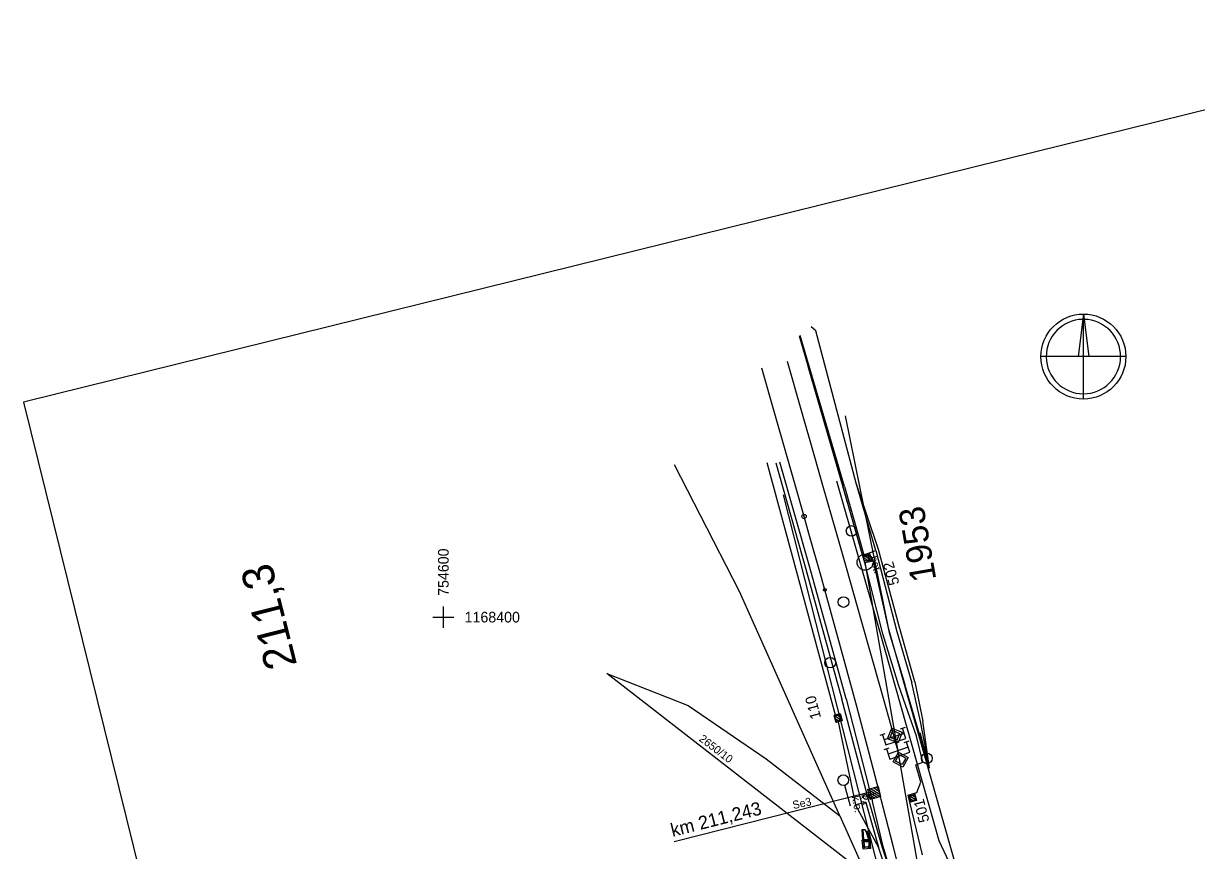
# Model space of a CAD drawing. Extents: x -754679 to -754173, y -1169241 to -1168288.
# Drawn here: x -754679.1 to -754458.2, y -1168443.9 to -1168288.2 of the extents above; entities that cross this region are included whole.
import ezdxf

# ---------------------------------------------------------------- set-up
doc = ezdxf.new("R2010")
doc.units = 0
for name, color, linetype in [('Default', 7, 'Continuous'), ('Vrstva 1', 7, 'Continuous'), ('Vrstva 11', 7, 'Continuous'), ('Vrstva 12', 7, 'Continuous'), ('Vrstva 13', 7, 'Continuous'), ('Vrstva 15', 7, 'Continuous'), ('Vrstva 16', 7, 'Continuous'), ('Vrstva 19', 7, 'Continuous'), ('Vrstva 2', 7, 'Continuous'), ('Vrstva 27', 7, 'Continuous'), ('Vrstva 3', 7, 'Continuous'), ('Vrstva 37', 7, 'Continuous'), ('Vrstva 4', 7, 'Continuous'), ('Vrstva 43', 7, 'Continuous'), ('Vrstva 49', 7, 'Continuous'), ('Vrstva 53', 7, 'Continuous'), ('Vrstva 55', 7, 'Continuous'), ('Vrstva 57', 7, 'Continuous'), ('Vrstva 6', 7, 'Continuous'), ('Vrstva 61', 7, 'Continuous'), ('Vrstva 63', 7, 'Continuous'), ('Vrstva 7', 7, 'Continuous')]:
    doc.layers.add(name, color=color, linetype=linetype)

msp = doc.modelspace()

# ---------------------------------------------------------------- linework, layer by layer
at = {"layer": 'Default'}
for points in [[(-754600, -1168402), (-754600, -1168400), (-754600, -1168398)], [(-754602, -1168400), (-754600, -1168400), (-754598, -1168400)]]:
    msp.add_lwpolyline(points, dxfattribs=at)
at = {"layer": 'Vrstva 1'}
for p, q in [((-754479.49, -1168342.95), (-754480.49, -1168350.95)), ((-754479.49, -1168358.95), (-754479.49, -1168342.95)), ((-754471.49, -1168350.95), (-754487.49, -1168350.95)), ((-754520.59, -1168389.67), (-754520.59, -1168389.67)), ((-754514.38, -1168425.11), (-754515.12, -1168422.49))]:
    msp.add_line(p, q, dxfattribs=at)
msp.add_lwpolyline([(-754479.49, -1168342.95), (-754478.49, -1168350.95), (-754479.49, -1168350.95)], close=True, dxfattribs=at)
for points in [[(-754515.12, -1168422.49), (-754517.72, -1168413.32), (-754521.2, -1168400.93), (-754522.02, -1168398.05), (-754524.11, -1168390.71), (-754525.99, -1168384.14), (-754528.54, -1168375.21), (-754530.06, -1168369.88), (-754532.62, -1168360.91), (-754535.19, -1168351.89)], [(-754532.08, -1168381.05), (-754533.64, -1168375.56), (-754535.53, -1168368.95), (-754537.58, -1168361.76), (-754540.04, -1168353.12)], [(-754513.35, -1168450.62), (-754515.29, -1168443.04), (-754517.54, -1168434.32), (-754517.92, -1168432.84), (-754519.83, -1168425.59), (-754522.16, -1168416.85), (-754524.53, -1168408.11), (-754526.91, -1168399.43), (-754528.18, -1168394.85), (-754528.89, -1168392.32), (-754531.16, -1168384.27), (-754532.08, -1168381.05)]]:
    msp.add_lwpolyline(points, dxfattribs=at)
for centre, radius in [((-754479.49, -1168350.95), 8), ((-754532.08, -1168381.05), 0.4), ((-754528.18, -1168394.85), 0.25)]:
    msp.add_circle(centre, radius, dxfattribs=at)
msp.add_arc((-754479.49, -1168350.95), 7, 91.0243, 88.9757, dxfattribs=at)
at = {"layer": 'Vrstva 11'}
for p, q in [((-754520.04, -1168389.36), (-754520.84, -1168388.92)), ((-754519.85, -1168389.03), (-754520.67, -1168388.59)), ((-754526.28, -1168418.61), (-754525.07, -1168419.32)), ((-754525.77, -1168418.48), (-754525.2, -1168418.81)), ((-754526.15, -1168419.12), (-754525.57, -1168419.46)), ((-754511.05, -1168434.41), (-754512.26, -1168433.7)), ((-754511.18, -1168433.9), (-754511.75, -1168433.56)), ((-754511.56, -1168434.55), (-754512.13, -1168434.21))]:
    msp.add_line(p, q, dxfattribs=at)
for points in [[(-754525.32, -1168418.36), (-754525.06, -1168419.32), (-754526.03, -1168419.58), (-754526.29, -1168418.61)], [(-754512.01, -1168434.66), (-754512.26, -1168433.69), (-754511.29, -1168433.44), (-754511.04, -1168434.41)]]:
    msp.add_lwpolyline(points, close=True, dxfattribs=at)
for points in [[(-754525.32, -1168418.36), (-754525.06, -1168419.32), (-754526.03, -1168419.58), (-754526.29, -1168418.61), (-754525.32, -1168418.36)], [(-754512.01, -1168434.66), (-754512.26, -1168433.69), (-754511.29, -1168433.44), (-754511.04, -1168434.41), (-754512.01, -1168434.66)]]:
    msp.add_lwpolyline(points, dxfattribs=at)
msp.add_circle((-754520.34, -1168388.97), 0.5, dxfattribs=at)
at = {"layer": 'Vrstva 12'}
for p, q in [((-754521.04, -1168388.46), (-754520.03, -1168388.21)), ((-754521.04, -1168388.46), (-754521.02, -1168388.47)), ((-754520.66, -1168389.78), (-754521.04, -1168388.46)), ((-754521.02, -1168388.47), (-754520.06, -1168388.23)), ((-754520.65, -1168389.75), (-754521.02, -1168388.47)), ((-754519.68, -1168389.54), (-754520.66, -1168389.78)), ((-754520.66, -1168389.78), (-754520.65, -1168389.75)), ((-754519.71, -1168389.5), (-754520.65, -1168389.75)), ((-754520.03, -1168388.21), (-754520.06, -1168388.23)), ((-754520.06, -1168388.23), (-754519.71, -1168389.5)), ((-754520.03, -1168388.21), (-754519.68, -1168389.54)), ((-754519.68, -1168389.54), (-754519.71, -1168389.5)), ((-754526.44, -1168418.55), (-754525.3, -1168418.18)), ((-754526.44, -1168418.55), (-754526.42, -1168418.54)), ((-754526.05, -1168419.82), (-754526.44, -1168418.55)), ((-754525.32, -1168418.21), (-754526.42, -1168418.54)), ((-754526.42, -1168418.54), (-754526.02, -1168419.79)), ((-754525.32, -1168418.21), (-754525.3, -1168418.18)), ((-754524.96, -1168419.45), (-754525.32, -1168418.21)), ((-754525.3, -1168418.18), (-754524.95, -1168419.47)), ((-754524.95, -1168419.47), (-754526.05, -1168419.82)), ((-754526.05, -1168419.82), (-754526.02, -1168419.79)), ((-754526.02, -1168419.79), (-754524.96, -1168419.45)), ((-754524.95, -1168419.47), (-754524.96, -1168419.45)), ((-754512.43, -1168433.46), (-754511.3, -1168433.17)), ((-754512.08, -1168434.83), (-754512.43, -1168433.46)), ((-754512.42, -1168433.55), (-754512.43, -1168433.46)), ((-754512.42, -1168433.55), (-754511.33, -1168433.21)), ((-754512.02, -1168434.8), (-754512.42, -1168433.55)), ((-754511.33, -1168433.21), (-754511.3, -1168433.17)), ((-754511.33, -1168433.21), (-754510.96, -1168434.46)), ((-754511.3, -1168433.17), (-754510.92, -1168434.5)), ((-754510.92, -1168434.5), (-754512.08, -1168434.83)), ((-754512.08, -1168434.83), (-754512.02, -1168434.8)), ((-754510.96, -1168434.46), (-754512.02, -1168434.8)), ((-754510.92, -1168434.5), (-754510.96, -1168434.46))]:
    msp.add_line(p, q, dxfattribs=at)
at = {"layer": 'Vrstva 13'}
for p, q in [((-754532.99, -1168347.06), (-754524.79, -1168375.35)), ((-754521, -1168388.43), (-754524.79, -1168375.35)), ((-754521.06, -1168388.47), (-754520.04, -1168388.16)), ((-754521, -1168388.43), (-754521.06, -1168388.47)), ((-754520.04, -1168388.16), (-754521, -1168388.43))]:
    msp.add_line(p, q, dxfattribs=at)
at = {"layer": 'Vrstva 15'}
for p, q in [((-754513.05, -1168420.77), (-754514, -1168421.08)), ((-754516.85, -1168422), (-754517.81, -1168422.31)), ((-754513.22, -1168421.88), (-754517.02, -1168423.11)), ((-754516.12, -1168424.66), (-754517.06, -1168424.99)), ((-754512.49, -1168424.46), (-754516.26, -1168425.77)), ((-754512.34, -1168423.35), (-754513.29, -1168423.67))]:
    msp.add_line(p, q, dxfattribs=at)
for points in [[(-754517.33, -1168422.15), (-754516.72, -1168424.06), (-754512.91, -1168422.83), (-754513.52, -1168420.93)], [(-754516.59, -1168424.82), (-754515.94, -1168426.71), (-754512.16, -1168425.4), (-754512.81, -1168423.51)]]:
    msp.add_lwpolyline(points, dxfattribs=at)
at = {"layer": 'Vrstva 16'}
for p, q in [((-754524.47, -1168375.41), (-754532.83, -1168347)), ((-754524.47, -1168375.41), (-754520.81, -1168388.26)), ((-754518.55, -1168387.44), (-754522.29, -1168374.75)), ((-754518.08, -1168387.29), (-754522.29, -1168374.75)), ((-754518.55, -1168387.44), (-754514.61, -1168402.71)), ((-754514.2, -1168401.73), (-754518.08, -1168387.29)), ((-754519.05, -1168389.49), (-754520.66, -1168389.8)), ((-754519.05, -1168389.49), (-754516.04, -1168402.91)), ((-754516.04, -1168402.91), (-754513.1, -1168412.7)), ((-754514.61, -1168402.71), (-754511.81, -1168412.37)), ((-754511.2, -1168412.17), (-754514.2, -1168401.73)), ((-754508.44, -1168428.42), (-754513.1, -1168412.7)), ((-754510.18, -1168419.65), (-754511.81, -1168412.37)), ((-754511.2, -1168412.17), (-754509.73, -1168419.6)), ((-754508.44, -1168428.42), (-754510.18, -1168419.65)), ((-754508.44, -1168428.42), (-754509.73, -1168419.6))]:
    msp.add_line(p, q, dxfattribs=at)
for points in [[(-754522.29, -1168374.75), (-754529.84, -1168346.11), (-754530.73, -1168345.35)], [(-754520.81, -1168388.26), (-754518.55, -1168387.44)], [(-754520.11, -1168388.2), (-754519.72, -1168389.51), (-754519.27, -1168389.39), (-754519.7, -1168388.08), (-754520.11, -1168388.2)]]:
    msp.add_lwpolyline(points, dxfattribs=at)
at = {"layer": 'Vrstva 19'}
for p, q in [((-754520.97, -1168440.02), (-754521.23, -1168440.03)), ((-754521.08, -1168440.04), (-754521.23, -1168440.03)), ((-754521.23, -1168440.03), (-754521.11, -1168441.95)), ((-754520.97, -1168440.02), (-754521.08, -1168440.04)), ((-754521.08, -1168440.04), (-754520.91, -1168441.96)), ((-754520.6, -1168440.07), (-754520.97, -1168440.02)), ((-754520.83, -1168441.94), (-754520.97, -1168440.02)), ((-754520.38, -1168440.38), (-754520.6, -1168440.07)), ((-754520.28, -1168440.38), (-754520.38, -1168440.38)), ((-754519.9, -1168441.9), (-754520.38, -1168440.38)), ((-754519.84, -1168441.88), (-754520.28, -1168440.38)), ((-754519.64, -1168441.85), (-754520.21, -1168440.3)), ((-754521.15, -1168442), (-754520.86, -1168441.98)), ((-754520.97, -1168443.7), (-754521.15, -1168442)), ((-754519.84, -1168441.88), (-754520.91, -1168441.96)), ((-754520.83, -1168441.94), (-754520.91, -1168441.96)), ((-754520.77, -1168443.38), (-754520.86, -1168441.98)), ((-754520.83, -1168441.94), (-754520.84, -1168442.2)), ((-754519.91, -1168442.11), (-754520.84, -1168442.2)), ((-754520.84, -1168442.2), (-754520.79, -1168442.28)), ((-754519.91, -1168442.11), (-754519.92, -1168442.21)), ((-754519.9, -1168441.9), (-754519.84, -1168441.88)), ((-754519.64, -1168441.87), (-754519.87, -1168441.9)), ((-754519.84, -1168441.88), (-754519.87, -1168441.9)), ((-754519.64, -1168441.85), (-754519.84, -1168441.88)), ((-754519.64, -1168441.87), (-754519.64, -1168441.85)), ((-754519.52, -1168443.58), (-754519.64, -1168441.87)), ((-754519.52, -1168443.58), (-754520.97, -1168443.7)), ((-754520.77, -1168443.38), (-754520.67, -1168443.31)), ((-754519.9, -1168443.33), (-754520.77, -1168443.38)), ((-754519.9, -1168443.33), (-754519.87, -1168443.22))]:
    msp.add_line(p, q, dxfattribs=at)
for points in [[(-754520.28, -1168440.38), (-754520.21, -1168440.3), (-754520.38, -1168440.38)], [(-754520.86, -1168441.98), (-754520.91, -1168441.96), (-754521.11, -1168441.95), (-754521.15, -1168442)], [(-754519.91, -1168442.11), (-754519.9, -1168441.9), (-754520.83, -1168441.94)], [(-754520.67, -1168443.31), (-754520.78, -1168442.28), (-754520.79, -1168442.28), (-754519.92, -1168442.21), (-754519.87, -1168443.22), (-754520.67, -1168443.31)], [(-754519.9, -1168443.33), (-754519.77, -1168443.23), (-754519.87, -1168441.9)]]:
    msp.add_lwpolyline(points, dxfattribs=at)
at = {"layer": 'Vrstva 27'}
msp.add_line((-754520.46, -1168433.77), (-754520.44, -1168433.87), dxfattribs=at)
msp.add_lwpolyline([(-754520.45, -1168433.82), (-754520.34, -1168433.75), (-754520.29, -1168433.54), (-754518.56, -1168433.16)], dxfattribs=at)
msp.add_circle((-754520.45, -1168433.82), 0.5, dxfattribs=at)
at = {"layer": 'Vrstva 3'}
for p, q in [((-754520.1, -1168432.36), (-754517.68, -1168433.81)), ((-754519.97, -1168432.87), (-754518.19, -1168433.94)), ((-754519.84, -1168433.39), (-754518.71, -1168434.07)), ((-754519.72, -1168433.9), (-754519.22, -1168434.2)), ((-754519.59, -1168432.23), (-754517.81, -1168433.3)), ((-754519.07, -1168432.1), (-754517.93, -1168432.78)), ((-754518.56, -1168431.97), (-754518.06, -1168432.27))]:
    msp.add_line(p, q, dxfattribs=at)
msp.add_lwpolyline([(-754518.16, -1168431.87), (-754517.68, -1168433.81), (-754519.62, -1168434.3), (-754520.1, -1168432.36)], close=True, dxfattribs=at)
at = {"layer": 'Vrstva 37'}
for p, q in [((-754509.23, -1168425.63), (-754510.21, -1168421.75)), ((-754508.98, -1168426.59), (-754508.98, -1168426.59)), ((-754524.7, -1168430.68), (-754524.7, -1168430.68)), ((-754524.44, -1168431.65), (-754523.42, -1168435.52))]:
    msp.add_line(p, q, dxfattribs=at)
for centre in [(-754508.98, -1168426.59), (-754524.7, -1168430.68)]:
    msp.add_circle(centre, 1, dxfattribs=at)
at = {"layer": 'Vrstva 4'}
for p, q in [((-754531.4, -1168352.75), (-754524.11, -1168377.88)), ((-754539.07, -1168370.89), (-754533.54, -1168391.49)), ((-754537.43, -1168370.97), (-754531.78, -1168390.96)), ((-754531.03, -1168390.67), (-754536.67, -1168370.8)), ((-754520.66, -1168389.8), (-754521.04, -1168388.48)), ((-754533.54, -1168391.49), (-754526.26, -1168418.41)), ((-754531.78, -1168390.96), (-754524.99, -1168415.42)), ((-754524.18, -1168415.41), (-754531.03, -1168390.67)), ((-754510.9, -1168422.41), (-754514.22, -1168412.95)), ((-754519.8, -1168434.85), (-754524.99, -1168415.42)), ((-754524.18, -1168415.41), (-754519.17, -1168434.71)), ((-754520.46, -1168434.9), (-754522.42, -1168435.31)), ((-754518.06, -1168443.28), (-754522.42, -1168435.31)), ((-754520.46, -1168434.9), (-754518.06, -1168443.28)), ((-754519.8, -1168434.85), (-754517.46, -1168443.17)), ((-754517.18, -1168443.16), (-754519.17, -1168434.71)), ((-754515.65, -1168450.55), (-754518.06, -1168443.28)), ((-754517.46, -1168443.17), (-754514.8, -1168451.12)), ((-754514.8, -1168451.12), (-754517.18, -1168443.16))]:
    msp.add_line(p, q, dxfattribs=at)
for points in [[(-754524.11, -1168377.88), (-754521.06, -1168388.47), (-754521.04, -1168388.48)], [(-754514.22, -1168412.95), (-754517.25, -1168403.13), (-754520.66, -1168389.8)], [(-754526.26, -1168418.41), (-754525.28, -1168418.16), (-754524.89, -1168419.45), (-754525.65, -1168419.74), (-754522.42, -1168435.31)], [(-754509.79, -1168444.75), (-754512.46, -1168433.52), (-754510.83, -1168432.99), (-754510.11, -1168431.07), (-754511.04, -1168427.82), (-754509.74, -1168427.31), (-754510.9, -1168422.41)]]:
    msp.add_lwpolyline(points, dxfattribs=at)
at = {"layer": 'Vrstva 43'}
for centre in [(-754523.14, -1168383.78), (-754524.66, -1168397.16), (-754527.18, -1168408.57)]:
    msp.add_circle(centre, 1, dxfattribs=at)
at = {"layer": 'Vrstva 49'}
for p, q in [((-754524.95, -1168419.47), (-754525.3, -1168418.18)), ((-754520.01, -1168443.07), (-754519.66, -1168443.43)), ((-754520.01, -1168443.43), (-754519.66, -1168443.07))]:
    msp.add_line(p, q, dxfattribs=at)
at = {"layer": 'Vrstva 53'}
for p, q in [((-754524.35, -1168362.13), (-754516.22, -1168402.04)), ((-754544.26, -1168395.2), (-754556.45, -1168371.36)), ((-754525.37, -1168437.38), (-754544.26, -1168395.2)), ((-754516.22, -1168402.04), (-754501.97, -1168452.25)), ((-754520.37, -1168448.54), (-754569.24, -1168410.61)), ((-754569.24, -1168410.61), (-754553.89, -1168416.63)), ((-754553.89, -1168416.63), (-754539.25, -1168426.67)), ((-754539.25, -1168426.67), (-754525.37, -1168437.38))]:
    msp.add_line(p, q, dxfattribs=at)
at = {"layer": 'Vrstva 55'}
for p, q in [((-754525.96, -1168374.32), (-754517.96, -1168402.36)), ((-754517.36, -1168450.11), (-754535.97, -1168376.96)), ((-754517.96, -1168402.36), (-754506.68, -1168442.02)), ((-754525.37, -1168437.38), (-754520.37, -1168448.54)), ((-754506.68, -1168442.02), (-754501.97, -1168452.25))]:
    msp.add_line(p, q, dxfattribs=at)
at = {"layer": 'Vrstva 6'}
for p, q in [((-754514.44, -1168422.3), (-754515.88, -1168422.72)), ((-754514.31, -1168425.39), (-754515.16, -1168422.51)), ((-754556.56, -1168442.22), (-754520.64, -1168433.13)), ((-754521.12, -1168433.24), (-754520.15, -1168433.03))]:
    msp.add_line(p, q, dxfattribs=at)
for points in [[(-754515.59, -1168420.92), (-754513.62, -1168421.68), (-754514.39, -1168423.65), (-754516.36, -1168422.89), (-754515.59, -1168420.92)], [(-754514.09, -1168421.89), (-754514.59, -1168423.19), (-754515.9, -1168422.69), (-754515.39, -1168421.37), (-754514.09, -1168421.89)], [(-754514.31, -1168425.39), (-754512.46, -1168426.4), (-754513.47, -1168428.26), (-754515.33, -1168427.25), (-754514.31, -1168425.39)], [(-754514.17, -1168425.87), (-754512.95, -1168426.54), (-754513.62, -1168427.77), (-754514.85, -1168427.11), (-754514.17, -1168425.87)]]:
    msp.add_lwpolyline(points, dxfattribs=at)
at = {"layer": 'Vrstva 61'}
msp.add_line((-754679.07, -1168359.54), (-754578.24, -1168767.26), dxfattribs=at)
msp.add_lwpolyline([(-754578.24, -1168767.26), (-754289.93, -1168695.96), (-754390.75, -1168288.24), (-754679.07, -1168359.54)], dxfattribs=at)
at = {"layer": 'Vrstva 63'}
msp.add_line((-754520.69, -1168389.67), (-754520.49, -1168389.67), dxfattribs=at)
msp.add_lwpolyline([(-754454.68, -1168695.98), (-754495.29, -1168534.73), (-754520.59, -1168389.67)], dxfattribs=at)
msp.add_circle((-754520.59, -1168389.67), 1.51, dxfattribs=at)

# ---------------------------------------------------------------- texts
at = {"layer": 'Default'}
msp.add_text('754600', height=2, rotation=90, dxfattribs=at).set_placement((-754599, -1168396))
msp.add_text('1168400', height=2, dxfattribs=at).set_placement((-754596, -1168401))
at = {"layer": 'Vrstva 11'}
for s, rotation, p in [('502', 106.4502, (-754514.1, -1168393.66)), ('110', 104.819, (-754528.86, -1168418.92)), ('501', 104.4696, (-754508.46, -1168438.38))]:
    msp.add_text(s, height=2, rotation=rotation, dxfattribs=at).set_placement(p)
at = {"layer": 'Vrstva 16'}
msp.add_text('bet.', height=1.5, rotation=286.5223, dxfattribs=at).set_placement((-754519.77, -1168388.72))
at = {"layer": 'Vrstva 2'}
msp.add_text('1953', height=4.8, rotation=99.8904, dxfattribs=at).set_placement((-754507.17, -1168392.91))
at = {"layer": 'Vrstva 27'}
msp.add_text('k.o.', height=1.5, rotation=281.7707, dxfattribs=at).set_placement((-754523.13, -1168433.76))
at = {"layer": 'Vrstva 57'}
msp.add_text('2650/10', height=1.5, rotation=322.7471, dxfattribs=at).set_placement((-754551.98, -1168423.18))
at = {"layer": 'Vrstva 6'}
for s, height, rotation, p in [('Se3', 1.5, 12.0953, (-754534.08, -1168436.14)), ('A A ', 1, 282.0953, (-754521.61, -1168433.34)), ('km 211,243', 2.5, 14.1985, (-754556.84, -1168441.38))]:
    msp.add_text(s, height=height, rotation=rotation, dxfattribs=at).set_placement(p)
at = {"layer": 'Vrstva 7'}
msp.add_text('211,3', height=6, rotation=104.1773, dxfattribs=at).set_placement((-754627.52, -1168408.97))

doc.saveas('drawing.dxf')
